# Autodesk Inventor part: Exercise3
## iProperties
Shininess: 64.0
Length Units: 11269
Angle Units: 11279
Time Units: 11290
Mass Units: 11283
Length Display Precision: 3
Angle Display Precision: 2
Compacted: True
Created: 2002-02
Part Number: Exercise3
Document SubType Name: Modeling
Density: 0.0
Volumn: 0.0
Area: 0.0
PropertySet Name: Model Information
Control State: 0
Master: False
Checked Out: False
